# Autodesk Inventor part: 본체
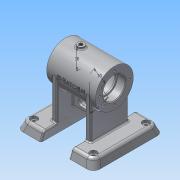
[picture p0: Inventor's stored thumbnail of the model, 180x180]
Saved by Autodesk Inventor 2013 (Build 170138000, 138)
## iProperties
Created: 2008-12
Part Number: 본체
Material: 알루미늄 6061
Document SubType Name: Modeling
Designer: Administrator
Density: 2.71 g/cm^3
Mass: 496.94 g
Surface Area: 538.478 cm^2
Volume: 183.373 cm^3
Author: Administrator
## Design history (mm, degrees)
sketch "스케치1"
  geometry: C1 r 27 at (0, 0); 1 further point
  constraints: 1 centre point, 1 coincident
  dimensions: "d0" = 54 diameter of C1
extrude "돌출1" new body sketch "스케치1" distance "d1" = 35; taper "d2" = 0 deg
sketch "스케치2"
  geometry: C1 r 27 at (0, 0) reference; C2 r 16 at (0, 0)
  constraints: 1 centre point, 1 coincident
  dimensions: "d3" = 32 diameter of C2
extrude "돌출2" cut sketch "스케치2" distance "d4" = 12; taper "d5" = 0 deg
sketch "스케치3"
  geometry: C1 r 16 at (0, 0) reference; C2 r 14 at (0, 0)
  constraints: 1 centre point, 1 coincident
  dimensions: "d6" = 28 diameter of C2
extrude "돌출3" cut sketch "스케치3" distance "d7" = 2; taper "d8" = 0 deg
sketch "스케치4"
  geometry: C1 r 14 at (0, 0) reference; C2 r 22 at (0, 0)
  constraints: 1 centre point, 1 coincident
  dimensions: "d9" = 44 diameter of C2
extrude "돌출4" cut sketch "스케치4" stored distance "d10" = 2; taper "d11" = 0 deg
chamfer "모따기1" distance "d12" = 1; stored, may be unused: second distance "d13" = 2, angle "d14" = 45 deg
fillet "모깎기1" dims "d15" = 0.3
sketch "스케치5"
  geometry: L1 (0, 0)-(0, 21); C1 r 17 at (0, 0) reference; 1 further point
  constraints: 2 end point, 1 coincident, 1 vertical
  dimensions: "d16" = 21 distance of L1.start L1.end
hole "구멍1" sketch "스케치5" at (0, 21) diameter "d17" = 3.242; stored, may be unused: countersink angle "d21" = 90 deg, drill point angle "d23" = 118 deg; dims "d18" = 8, "d19" = 4, "d20" = 2, "d22" = 10
fillet "모깎기2" dims "d27" = 2
node "작업 평면1"
node "작업 평면3"
sketch "스케치9"
  geometry: L1 (0, 0)-(-30, 0)
  constraints: 2 end point, 1 horizontal
  dimensions: "d44" = 30 distance of L1.start L1.end
node "작업 평면4"
sketch "스케치10"
  geometry: L1 (-22, -27)-(-22, 27) reference; L2 (48, -27)-(48, 27) reference; C1 r 5 at (0, 0); 4 further points
  constraints: 1 centre point, 1 coincident
  dimensions: "d45" = 10 diameter of C1
extrude "돌출6" join sketch "스케치10" stored distance "d46" = 2; taper "d47" = 0 deg
sketch "스케치11"
  geometry: C1 r 5 at (0, 0) reference; 2 further points
  constraints: 1 coincident
hole "구멍3" sketch "스케치11" at (0, 0) diameter "d48" = 5.188; stored, may be unused: countersink angle "d52" = 90 deg, drill point angle "d54" = 118 deg; dims "d49" = 99, "d50" = 4, "d51" = 2, "d53" = 10
fillet "모깎기4" dims "d55" = 2
node "작업 평면5"
sketch "스케치13"
  geometry: L1 (0, 0)-(9.92, 0); L2 (0, 0)-(25.441, 15.898)
  constraints: 4 end point, 1 horizontal
  dimensions: "d57" = 30 distance of L1.start L2.end; "d58" = 32 deg angle of L1 L2
node "작업 평면6"
sketch "스케치14"
  geometry: C1 r 6 at (0, 0); 1 further point
  constraints: 1 centre point, 1 coincident
  dimensions: "d59" = 12 diameter of C1
extrude "돌출7" join sketch "스케치14" stored distance "d60" = 2; taper "d61" = 0 deg
fillet "모깎기5" dims "d62" = 2
hole "구멍4" diameter "d65" = 5.188; stored, may be unused: countersink angle "d69" = 90 deg, drill point angle "d71" = 118 deg; dims "d63" = 10, "d64" = 10, "d66" = 99, "d67" = 4, "d68" = 2, "d70" = 10
node "작업 평면8"
  node "작업 평면7"
sketch "스케치16"
  geometry: L1 (-55, -50)-(55, -50); L2 (55, -50)-(55, 50); L3 (55, 50)-(-55, 50); L4 (-55, 50)-(-55, -50); L5 (-55, -50)-(55, 50); L6 (55, -50)-(-55, 50); 1 further point
  constraints: 12 end point, 2 midpoint, 2 parallel, 1 horizontal, 1 perpendicular
  dimensions: "d74" = 110 distance of L3.end L2.end; "d75" = 100 distance of L2.end L1.end
extrude "돌출8" join sketch "스케치16" distance "d76" = 12; taper "d77" = 0 deg
sketch "스케치17"
  geometry: L1 (0, 0)-(110, 0) reference; L2 (110, 0)-(110, 12) reference; L3 (0, 12)-(110, 12) reference; L4 (105.632, 12)-(110, 0); 1 further point
  constraints: 2 end point, 1 point on line
  dimensions: "d78" = 110 deg angle of L1 L4
extrude "돌출9" cut sketch "스케치17" stored distance "d79" = 12; taper "d80" = 0 deg
sketch "스케치18"
  geometry: L1 (0, 100)-(0, 0) reference; L2 (0, 0)-(12, 0) reference; L3 (12, 100)-(12, 0) reference; L4 (0, 0)-(12, 4.368); 1 further point
  constraints: 2 end point, 1 point on line
  dimensions: "d81" = 110 deg angle of L1 L4
extrude "돌출10" cut sketch "스케치18" stored distance "d82" = 12; taper "d83" = 0 deg
fillet "모깎기6" dims "d84" = 10
fillet "모깎기7" dims "d85" = 5
sketch "스케치19"
  geometry: L1 (-20, 4)-(20, 4); L2 (20, 4)-(20, -4); L3 (20, -4)-(-20, -4); L4 (-20, -4)-(-20, 4); L5 (-20, 4)-(20, -4); L6 (20, 4)-(-20, -4); L7 (20, -4)-(-20, -4); L8 (-20, -4)-(-20, -60.931); L9 (-20, -60.931)-(20, -60.931); L10 (20, -60.931)-(20, -4); L11 (20, 4)-(-20, 4); L12 (-20, 4)-(-20, 65.764); L13 (-20, 65.764)-(20, 65.764); L14 (20, 65.764)-(20, 4); 1 further point
  constraints: 28 end point, 6 parallel, 3 horizontal, 3 perpendicular, 2 midpoint
  dimensions: "d86" = 40 distance of L2.end L3.end; "d87" = 8 distance of L1.end L2.end
extrude "돌출11" cut sketch "스케치19" distance "d88" = 12; taper "d89" = 0 deg
sketch "스케치20"
  geometry: L1 (-20, -42.131)-(-20, 42.131) reference; L2 (-28, 27)-(-20, 27); L3 (-20, 27)-(-20, -27); L4 (-20, -27)-(-28, -27); L5 (-28, -27)-(-28, 27); 2 further points
  constraints: 8 end point, 2 midpoint, 2 parallel, 1 horizontal, 1 perpendicular
  dimensions: "d90" = 8 distance of L3.end L4.end; "d91" = 54 distance of L2.end L3.end
extrude "돌출12" join sketch "스케치20" stored distance "d92" = 12; taper "d93" = 0 deg
fillet "모깎기8" dims "d94" = 2
fillet "모깎기9" dims "d95" = 2
fillet "모깎기10" dims "d96" = 2
node "작업 평면10"
  node "작업 평면9"
sketch "스케치22"
  geometry: L1 (20, -47.872)-(20, 47.872) reference; L2 (-20, -4)-(20, -4); L3 (20, -4)-(20, 4); L4 (20, 4)-(-20, 4); L5 (-20, 4)-(-20, -4); L6 (-20, -4)-(20, 4); L7 (20, -4)-(-20, 4); 1 further point
  constraints: 12 end point, 2 midpoint, 2 parallel, 1 horizontal, 1 perpendicular, 1 point on line
  dimensions: "d113" = 8 distance of L3.end L2.end
extrude "돌출13" join sketch "스케치22" stored distance "d114" = 12; taper "d115" = 0 deg
sketch "스케치23"
  geometry: L1 (12, 13.5)-(28, 13.5); L2 (28, 6.5)-(12, 6.5); L3 (20, 6.5)-(20, 13.5); L4 (55, 21)-(55, 75) reference; L5 (42, -22)-(65.603, -22) reference; A1 r 3.5 centre (28, 10) between (28, 6.5) and (28, 13.5); A2 r 3.5 centre (12, 10) between (12, 13.5) and (12, 6.5); 1 further point
  constraints: 6 end point, 4 point on circle, 4 tangent, 2 centre point, 2 midpoint, 1 horizontal alignment
  dimensions: "d116" = 7 diameter of A1; "d117" = 7 diameter of A2; "d118" = 23 dimension on A1 A2; "d119" = 35 distance between parallel lines of L4 L3; "d120" = 11.5 dimension on A2 L3 (derived); "d121" = 32 distance from line of A1.centre L5
extrude "돌출14" cut sketch "스케치23" distance "d122" = 12; taper "d123" = 0 deg
fillet "모깎기11" dims "d124" = 2
fillet "모깎기12" dims "d125" = 2
fillet "모깎기13" dims "d126" = 2
sketch "스케치24"
  geometry: L1 (42.5, -37.5)-(-42.5, -37.5); L2 (-42.5, -37.5)-(-42.5, 37.5); L3 (-42.5, 37.5)-(42.5, 37.5); L4 (42.5, 37.5)-(42.5, -37.5); L5 (42.5, -37.5)-(-42.5, 37.5); L6 (-42.5, -37.5)-(42.5, 37.5); A1 r 5 centre (-42.5, 37.5) between (-47.131, 35.616) and (-40.616, 42.131) reference; 5 further points
  constraints: 12 end point, 4 coincident, 2 midpoint, 2 parallel, 1 horizontal, 1 perpendicular
  dimensions: "d127" = 85 distance of L2.end L3.end (derived); "d128" = 75 distance of L1.end L2.end (derived)
hole "구멍6" sketch "스케치24" at (-42.5, -37.5), (42.5, -37.5), (42.5, 37.5), (-42.5, 37.5) diameter "d129" = 6; stored, may be unused: countersink angle "d133" = 90 deg, drill point angle "d135" = 118 deg; dims "d130" = 99, "d131" = 10, "d132" = 4, "d134" = 10
fillet "모깎기14" dims "d136" = 2
node "작업 평면11"
sketch "스케치25"
  geometry: L1 (-35, -27)-(-35, 27) reference; L2 (-35, 27)-(35, 27) reference; 2 further points
  constraints: 1 other
  dimensions: "d137" = 35 distance from line of L1 point (0, 0); "d138" = 27 distance from line of L2 point (0, 0)
feature "엠보싱1" sketch "스케치25" dims "d139" = 0.5, "d140" = 0
node "솔리드1"
pattern_circular "원형 패턴1" dims angle "d25" = 360 deg
mirror "대칭1"
mirror "대칭2"
mirror "대칭3"
mirror "대칭4"
node "투영된 루프1"
other parameters: "d28" = -22, "d43" = -48, "d56" = -35, "d112" = -21
